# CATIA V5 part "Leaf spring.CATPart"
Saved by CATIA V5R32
Part number: Part1
Material "Steel": density 7860 kg/m3, Young's modulus 2e+11 Pa, Poisson ratio 0.266, thermal expansion 1.17e-05 1/K
Bounding box of the stored display mesh (mm): x 0 to 6, y -52.464 to 52.464, z -1 to 10.425
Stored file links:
  D:\PROJECTS\Project 2022\CATIA V5 6R 2022\Resources\Input file\c19_catia_v5_6r2022_inp\c19_catia_v5_6r2022_inp\c19_catia_v5_6r2022_inp\C19_tut_03.CATPart\Leaf spring.CATPart
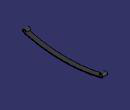
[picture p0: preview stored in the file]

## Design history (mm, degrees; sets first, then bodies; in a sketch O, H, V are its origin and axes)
Body1 (main body), material "Steel"
  Sketch1 on yz-plane, origin (0, 0, 0), H (0, 1, 0), V (0, 0, 1)
    arc A1 centre (0, 199) radius 199 from (-50.3797, 6.4828) to (50.3797, 6.4828) ccw
    point P1 (0, 199)
    arc A2 centre (0, 199) radius 200 from (-50.6329, 5.5154) to (50.6329, 5.5154) ccw
    arc A3 centre (-50, 7.9339) radius 2.5 from (-47.5, 7.9339) to (-50.6329, 5.5154) ccw
    point P2 (-50, 7.9339)
    arc A4 centre (50, 7.9339) radius 2.5 from (47.5, 7.9339) to (50.6329, 5.5154) cw
    arc A5 centre (-50, 7.9339) radius 1.5 from (-48.5, 7.9339) to (-50.3797, 6.4828) ccw
    point P4 (50, 7.9339)
    arc A6 centre (50, 7.9339) radius 1.5 from (48.5, 7.9339) to (50.3797, 6.4828) cw
    point P8 (50.3797, 6.4828)
    line L1 (48.5, 7.9339) -> (47.5, 7.9339)
    point P10 (-47.5, 7.9339)
    point P11 (50.3797, 6.4828)
    line L2 (-47.5, 7.9339) -> (-48.5, 7.9339)
    distance A1 A2 = 1
    distance P4 P2 = 100
    radius A3 = 2.5
    radius A2 = 200
    coincidence: A1 O, P1 V, A6 P8, L1 P10, A1 P11, L1 L2, L2 P2
    concentricity: A1 A2
    tangency: A3 A2, A5 A1
    symmetry: A3 A4 V, A5 A6 V
    horizontal: L1 H, L2 H
  Pad1: profile Sketch1, direction (1, 0, 0), length 6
